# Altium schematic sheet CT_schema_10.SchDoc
size 147 x 119 mm
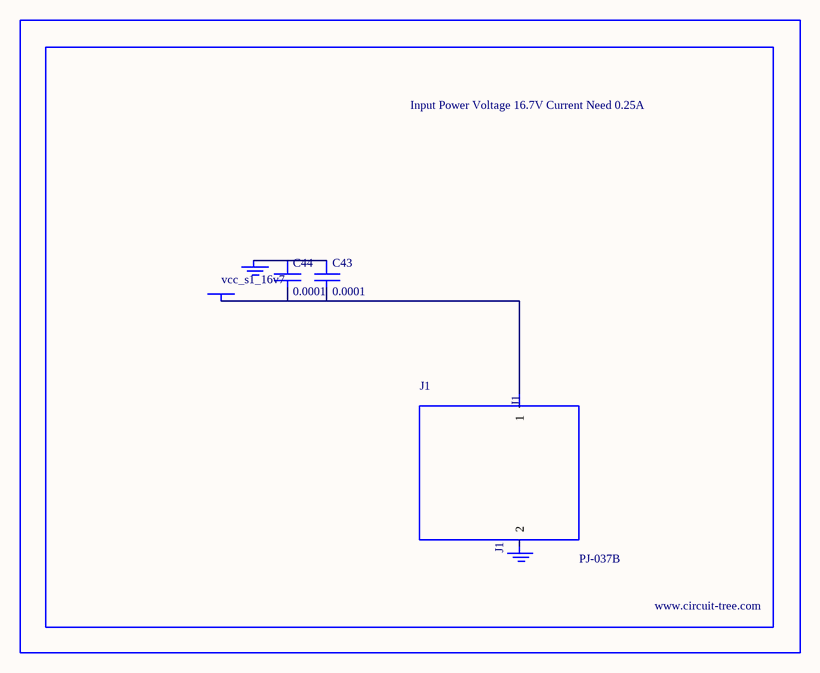
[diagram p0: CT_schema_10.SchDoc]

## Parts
BORDER9  (no value)
C43  0.0001  [EXV-9H]
C44  0.0001  [EXV-9H]
GND_INSTANCE_9_0  (no value)
GND_INSTANCE_9_1  (no value)
J1  PJ-037B  [PJ-037B_PACKAGE]
POWER_INSTANCE_9_0  vcc_s1_16v7

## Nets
NetC43_1: C43.1 C44.1 GND_INSTANCE_9_0.0(GND)
NetC43_2: C43.2 C44.2 J1.1 POWER_INSTANCE_9_0.0(PWR)

Not connected (* = marked no-connect by the designer): GND_INSTANCE_9_1 0(GND); J1 2

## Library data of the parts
BORDER9 = BORDER_PAGE9
C43 C44 = EDK107M035A9HAA
GND_INSTANCE_9_0 GND_INSTANCE_9_1 = GND
POWER_INSTANCE_9_0 = PWR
